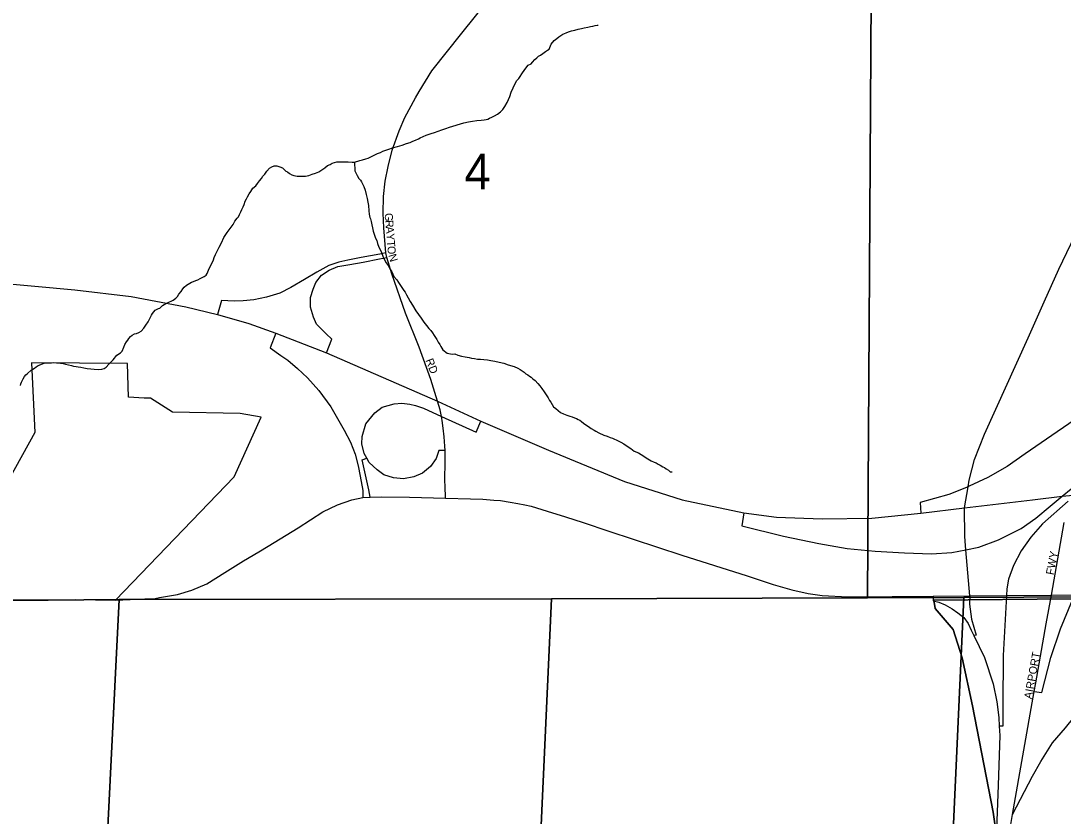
# Model space of a CAD drawing. Extents: x 2010165 to 2382125, y 1060529 to 1407316.
# Drawn here: x 2146217 to 2152727, y 1244739 to 1249704 of the extents above; entities that cross this region are included whole.
import ezdxf

# ---------------------------------------------------------------- set-up
doc = ezdxf.new("R2010")
doc.units = 0
for name, color, linetype in [('GM_X_City_Street', 7, 'Continuous'), ('GM_X_City_Street_Text', 7, 'Continuous'), ('GM_X_Corporation', 7, 'Continuous'), ('GM_X_Interchange_Ramps', 7, 'Continuous'), ('GM_X_Interstate_Route', 7, 'Continuous'), ('GM_X_Minor_River', 7, 'Continuous'), ('GM_X_Section', 7, 'Continuous'), ('GM_X_Section_Text', 7, 'Continuous'), ('GM_X_State_Route', 7, 'Continuous')]:
    doc.layers.add(name, color=color, linetype=linetype)

msp = doc.modelspace()

# ---------------------------------------------------------------- linework, layer by layer
at = {"layer": 'GM_X_City_Street'}
for points in [[(2148705.3, 1249263.5), (2148782.9, 1249391.8), (2148971.4, 1249627.1), (2149244.4, 1249968.5), (2149566.8, 1250337.8), (2149744.1, 1250550), (2149810.3, 1250647.6), (2149864.3, 1250752.2), (2149904.4, 1250860.3), (2149937, 1250974.5), (2149998, 1251300.5), (2150083.5, 1251782.8)], [(2148859.8, 1247107), (2148854.4, 1247159.9), (2148847.9, 1247208.4), (2148843, 1247234.5), (2148835.4, 1247275.8), (2148818.7, 1247328.9), (2148777.8, 1247463.9), (2148703.5, 1247666.6), (2148619.2, 1247878.6), (2148534.2, 1248124.8), (2148501.8, 1248226.4), (2148496.2, 1248255.4), (2148483.5, 1248412.5), (2148480.6, 1248503.1), (2148482.1, 1248606.5), (2148492, 1248702.8), (2148510.4, 1248794.8), (2148536.1, 1248895.5), (2148580, 1249016.6), (2148615.6, 1249100.9), (2148680.9, 1249223.2), (2148705.3, 1249263.5)], [(2148869.9, 1246722.9), (2148866.4, 1246800.4), (2148865.1, 1246829.1), (2148866.4, 1246958.4), (2148866, 1247021.3), (2148865.8, 1247048.4), (2148859.8, 1247107)], [(2152621.6, 1245939.2), (2152653.4, 1246119.1), (2152733.6, 1246572.2)], [(2152556.3, 1245569.9), (2152621.6, 1245939.2)], [(2152411, 1244747.8), (2152547, 1245517.1), (2152556.3, 1245569.9)]]:
    msp.add_lwpolyline(points, dxfattribs=at)
at = {"layer": 'GM_X_Corporation'}
for points in [[(2145721.8, 1246089.3), (2146557.6, 1246091.4), (2146807.3, 1246086.3), (2147548.1, 1246856.1), (2147717.4, 1247229.8), (2147586.4, 1247252.2), (2147163.9, 1247261.4), (2147026.1, 1247348.8), (2146986, 1247348), (2146889.8, 1247354.1), (2146883.7, 1247564.5), (2146283, 1247568.4), (2146303.5, 1247133.8), (2146005.5, 1246598.5)], [(2152310.6, 1244620.1), (2152289.8, 1244764), (2152160.8, 1245427.1), (2152096.9, 1245726.6), (2152039.4, 1245903.8), (2151926.8, 1246035.9), (2151919.8, 1246085.9), (2152779.7, 1246094.4)], [(2152779.7, 1246094.4), (2151919.8, 1246085.9), (2151926.8, 1246035.9), (2152039.4, 1245903.8), (2152096.9, 1245726.6), (2152160.8, 1245427.1), (2152289.8, 1244764), (2152310.6, 1244620.1)]]:
    msp.add_lwpolyline(points, dxfattribs=at)
at = {"layer": 'GM_X_Interchange_Ramps'}
for points in [[(2148496.2, 1248255.4), (2148458.9, 1248246.8), (2148342.3, 1248225.4), (2148258.9, 1248210.1), (2148202.3, 1248198.1), (2148140.9, 1248176.1), (2148066.3, 1248134.1), (2147989.1, 1248089), (2147903.6, 1248038.8), (2147834.2, 1248003.9), (2147751.3, 1247977.7), (2147672.7, 1247962.4), (2147605.1, 1247955.9), (2147548.4, 1247953.7), (2147509.1, 1247955.9), (2147469.9, 1247958.1), (2147445.6, 1247870.8)], [(2148126.6, 1247630.8), (2148159.3, 1247715.9), (2148122.9, 1247749.3), (2148063.3, 1247809.7), (2148043.7, 1247853.3), (2148026.2, 1247916.6), (2148026.3, 1247976.8), (2148041.5, 1248027.9), (2148058.9, 1248069.3), (2148093.8, 1248115.2), (2148141.8, 1248147.9), (2148196.9, 1248169.5), (2148270.6, 1248182.8), (2148355.6, 1248198.1), (2148456, 1248217.7), (2148501.8, 1248226.4)], [(2147809.6, 1247753.5), (2147773.6, 1247662.1), (2147840.3, 1247615.5), (2147884.3, 1247584.8), (2147944.3, 1247533.5), (2148007.6, 1247475.5), (2148077.6, 1247396.2), (2148152.3, 1247294.2), (2148235.6, 1247148.2), (2148276.2, 1247072.9), (2148304.4, 1246999.2), (2148323.6, 1246926.3), (2148337, 1246861.2), (2148352.4, 1246771), (2148351.8, 1246728.1)], [(2150732.1, 1246631.2), (2150720, 1246551.3), (2150979.3, 1246486.8), (2151201.7, 1246441.1), (2151378, 1246409.1), (2151552.9, 1246392), (2151736.2, 1246381.6), (2151904.2, 1246375.8), (2152032, 1246384.3), (2152119.1, 1246401.5), (2152199.4, 1246417.3), (2152323.7, 1246464.4), (2152464, 1246533.9), (2152556.8, 1246599.1), (2152645.8, 1246672.9), (2152720.3, 1246735.4), (2152776.9, 1246782.9), (2153276.7, 1247202.3), (2153303.4, 1247223.8), (2153452.3, 1247343.7), (2153542.4, 1247405.7), (2153625, 1247452), (2153693.6, 1247486.4), (2153668.7, 1247553.2)], [(2153547.8, 1247510.5), (2153538, 1247546.7), (2153138.2, 1247413.1), (2153032.3, 1247363.9), (2152929.6, 1247302.3), (2152490.1, 1247000.1), (2152377.2, 1246920.5), (2152255.9, 1246852.4), (2152140.3, 1246797.8), (2152132.8, 1246794.8), (2152012.5, 1246745.7), (2151834.7, 1246697.4), (2151838.2, 1246630.9)], [(2148866, 1247021.3), (2148828.4, 1247021.7), (2148809.9, 1246970.8), (2148775.3, 1246922.3), (2148724.4, 1246880.8), (2148671.3, 1246857.7), (2148606.7, 1246843.8), (2148544.3, 1246850.8), (2148484.3, 1246869.2), (2148442.7, 1246901.6), (2148391.9, 1246945.4), (2148377.4, 1246973.2), (2148361.9, 1247003.2), (2148347.3, 1247062.5), (2148348, 1247109.5), (2148371.1, 1247187.9), (2148426.6, 1247256), (2148472.7, 1247291.9), (2148549.4, 1247313.7), (2148596.6, 1247316.7), (2148646.4, 1247311.1), (2148681.6, 1247302.9), (2148732.1, 1247285.1), (2148843, 1247234.5), (2149059.9, 1247135.7), (2149090.1, 1247204.3)], [(2148399.2, 1246729.9), (2148390.7, 1246775.8), (2148348.5, 1246963.7), (2148377.4, 1246973.2)], [(2152547, 1245517.1), (2152593.1, 1245510.1), (2152649.9, 1245729.4), (2152709.9, 1245907.1), (2152784.5, 1246090), (2152797.6, 1246120.6), (2152838.3, 1246216), (2152902.4, 1246317.8), (2152966.8, 1246404.9), (2153031.3, 1246487.1), (2153108.2, 1246557.3), (2153214.5, 1246633), (2153321.1, 1246694), (2153432.9, 1246740.4), (2153520.7, 1246761.7), (2153559.2, 1246770.7), (2153553.8, 1246822.3)], [(2152759.2, 1246705.7), (2152598.6, 1246563.8), (2152526, 1246480.5), (2152463.9, 1246394.9), (2152416.4, 1246302.9), (2152385.9, 1246219), (2152374.7, 1246158.1), (2152372.4, 1246116.1), (2152352.7, 1245741.3), (2152351, 1245431.8), (2152349.4, 1245301.2), (2152327.8, 1245299.8)], [(2151915, 1246111.3), (2151914.9, 1246082.3), (2151950.9, 1246074.6), (2151990.2, 1246057.5), (2152032.9, 1246033.1), (2152069.2, 1246008.5), (2152105.7, 1245977.7), (2152132.8, 1245941.3), (2152152.6, 1245899.6), (2152170.1, 1245866.2), (2152235.7, 1245728.3), (2152290.5, 1245565.3), (2152312.4, 1245453), (2152324.3, 1245355.2), (2152327.8, 1245299.8), (2152331.5, 1245242.6), (2152320.8, 1244931.1), (2152308.9, 1244597.7), (2152384.4, 1244584.3)], [(2152144, 1246113.6), (2152143, 1246062.2), (2152155.5, 1245967.8), (2152183.2, 1245869.4), (2152170.1, 1245866.2)]]:
    msp.add_lwpolyline(points, dxfattribs=at)
at = {"layer": 'GM_X_Interstate_Route'}
for points in [[(2145362.6, 1248149.4), (2145699, 1248127.3), (2145984, 1248075.9), (2146303.1, 1248046.5)], [(2146303.1, 1248046.5), (2146553.5, 1248023.5), (2146904.8, 1247982.1), (2147246.3, 1247918.8), (2147445.6, 1247870.8), (2147640.3, 1247814.1), (2147809.6, 1247753.5), (2148126.6, 1247630.8), (2148818.7, 1247328.9)], [(2148818.7, 1247328.9), (2149090.1, 1247204.3), (2149512.2, 1247022.9), (2149986.3, 1246827.7), (2150348.1, 1246712.4), (2150732.1, 1246631.2)], [(2150732.1, 1246631.2), (2150936.8, 1246605.6), (2151222.2, 1246594.1), (2151531.1, 1246599.9), (2151838.2, 1246630.9), (2152111.5, 1246663.3), (2152534.6, 1246713.4)], [(2152534.6, 1246713.4), (2152720.3, 1246735.4), (2152767.2, 1246741), (2152804.1, 1246745.3), (2152815.8, 1246746.7), (2153017.1, 1246767.3)]]:
    msp.add_lwpolyline(points, dxfattribs=at)
at = {"layer": 'GM_X_Minor_River'}
for points in [[(2148597.8, 1248928.2), (2148625.7, 1248938.7), (2148647.6, 1248945.2), (2148665.5, 1248953.6), (2148681.4, 1248959.9), (2148699.4, 1248966.2), (2148711.3, 1248972.5), (2148729.2, 1248980.8), (2148749.1, 1248989.3), (2148779, 1248999.9), (2148801, 1249006.3), (2148822.9, 1249014.8), (2148846.8, 1249023.2), (2148870.8, 1249031.7), (2148894.7, 1249040.2), (2148982.5, 1249068), (2149012.5, 1249072.6), (2149038.5, 1249077.1), (2149064.5, 1249081.6), (2149092.5, 1249084.1), (2149110.5, 1249086.5), (2149122.5, 1249088.8), (2149132.5, 1249090.9), (2149144.5, 1249095.2), (2149158.4, 1249101.5), (2149174.3, 1249111.8), (2149194.2, 1249122.2), (2149212, 1249136.6), (2149227.7, 1249151), (2149239.4, 1249169.2), (2149255, 1249193.6), (2149262.7, 1249211.8), (2149270.4, 1249232.1), (2149279.9, 1249258.3), (2149291.5, 1249284.6), (2149303.1, 1249308.9), (2149314.7, 1249331.2), (2149326.5, 1249343.5), (2149336.3, 1249355.8), (2149346, 1249374), (2149363.6, 1249400.4), (2149385.2, 1249426.9), (2149403.1, 1249435.3), (2149412.9, 1249445.5), (2149426.6, 1249461.8), (2149438.5, 1249472.1), (2149450.3, 1249482.4), (2149462.2, 1249490.6), (2149476.1, 1249500.9), (2149493.9, 1249513.3), (2149505.8, 1249521.6), (2149515.7, 1249527.8), (2149529.2, 1249558.1), (2149548.8, 1249580.6), (2149564.7, 1249592.9), (2149576.5, 1249603.2), (2149602.3, 1249619.7), (2149622.2, 1249628.1), (2149638.2, 1249634.5), (2149656.1, 1249640.8), (2149676.1, 1249645.2), (2149698, 1249651.7), (2149718, 1249656.1), (2149736, 1249660.4), (2149758, 1249664.9), (2149774, 1249669.2), (2149790, 1249671.5), (2149804, 1249673.8), (2149816, 1249676), (2149822, 1249676.1)], [(2147101.3, 1247926.1), (2147123.1, 1247938.6), (2147159, 1247955.3), (2147168.9, 1247959.5), (2147184.7, 1247971.9), (2147194.6, 1247982.1), (2147204.3, 1247998.3), (2147218, 1248014.6), (2147227.8, 1248030.9), (2147237.6, 1248041.1), (2147251.4, 1248053.4), (2147261.4, 1248059.6), (2147271.3, 1248065.8), (2147283.2, 1248072.1), (2147295.2, 1248076.3), (2147309.1, 1248082.6), (2147321.1, 1248086.9), (2147337, 1248095.2), (2147348.9, 1248101.4), (2147360.8, 1248107.7), (2147374.7, 1248116), (2147380.5, 1248126.1), (2147388.2, 1248146.3), (2147399.8, 1248170.7), (2147411.4, 1248192.9), (2147419.1, 1248211.2), (2147424.8, 1248227.3), (2147432.5, 1248245.5), (2147442.1, 1248265.8), (2147455.7, 1248290.1), (2147469.3, 1248318.5), (2147484.7, 1248350.9), (2147504.2, 1248381.4), (2147543.4, 1248432.3), (2147553.1, 1248452.6), (2147566.8, 1248470.9), (2147576.6, 1248481.1), (2147582.4, 1248495.3), (2147590.1, 1248511.5), (2147597.8, 1248525.7), (2147605.6, 1248541.9), (2147611.3, 1248558), (2147616.9, 1248578.2), (2147626.7, 1248592.4), (2147632.5, 1248604.6), (2147642.2, 1248622.8), (2147653.9, 1248639.1), (2147665.6, 1248659.4), (2147683.4, 1248673.8), (2147695.2, 1248688.1), (2147706.9, 1248704.4), (2147718.7, 1248718.6), (2147728.4, 1248734.9), (2147740.2, 1248747.1), (2147753.9, 1248765.5), (2147769.6, 1248783.8), (2147783.5, 1248792.1), (2147799.5, 1248798.5), (2147815.5, 1248798.8), (2147833.7, 1248793.1), (2147849.9, 1248785.4), (2147862.1, 1248775.6), (2147872.3, 1248765.7), (2147882.4, 1248761.9), (2147894.7, 1248750.1), (2147908.9, 1248742.4), (2147921, 1248738.6), (2147931.1, 1248736.8), (2147943.1, 1248735), (2147953.2, 1248733.2), (2147995.3, 1248734), (2148015.3, 1248738.4), (2148035.2, 1248746.8), (2148057.2, 1248753.2), (2148077.1, 1248761.6), (2148096.9, 1248774.1), (2148114.8, 1248786.4), (2148132.5, 1248800.8), (2148148.5, 1248807.1), (2148160.4, 1248815.4), (2148176.3, 1248819.7), (2148190.3, 1248824), (2148208.4, 1248824.4), (2148232.5, 1248822.8), (2148260.6, 1248823.4), (2148286.7, 1248821.8), (2148300.7, 1248822.1), (2148334.6, 1248832.8), (2148350.6, 1248837.1), (2148370.6, 1248841.5), (2148386.6, 1248845.8), (2148402.5, 1248854.2), (2148424.4, 1248864.6), (2148444.2, 1248875), (2148462.2, 1248881.4), (2148478.1, 1248889.7), (2148496, 1248896.1), (2148516, 1248902.5), (2148537.9, 1248911), (2148569.8, 1248919.6), (2148597.8, 1248928.2)], [(2148300.7, 1248822.1), (2148303.7, 1248768), (2148316.3, 1248738.1), (2148328.7, 1248720.3), (2148339, 1248708.5), (2148345.2, 1248698.5), (2148351.4, 1248686.6), (2148359.8, 1248668.7), (2148366.2, 1248646.8), (2148372.7, 1248618.8), (2148379.2, 1248594.8), (2148383.6, 1248572.8), (2148388, 1248550.8), (2148390.7, 1248516.8), (2148393.1, 1248496.8), (2148395.3, 1248486.8), (2148397.4, 1248476.8), (2148399.6, 1248466.8), (2148404, 1248450.8), (2148417.1, 1248390.8), (2148432, 1248347), (2148440.3, 1248333.1), (2148444.6, 1248313.1), (2148453.1, 1248291.2), (2148461.4, 1248275.3), (2148469.8, 1248257.4), (2148478.2, 1248235.5), (2148488.7, 1248211.6), (2148499, 1248193.7), (2148511.4, 1248175.9), (2148521.8, 1248156), (2148534.2, 1248136.2), (2148546.8, 1248108.4), (2148565.3, 1248086.6), (2148575.6, 1248070.8), (2148600.4, 1248033.1), (2148608.6, 1248021.2), (2148616.9, 1248009.4), (2148625.2, 1247993.5), (2148635.6, 1247973.6), (2148648, 1247951.8), (2148662.5, 1247927.9), (2148683.2, 1247894.2), (2148699.7, 1247870.5), (2148716.2, 1247846.7), (2148734.7, 1247823), (2148751.2, 1247801.2), (2148765.5, 1247783.4), (2148777.8, 1247769.6), (2148788.1, 1247755.8), (2148798.5, 1247739.9), (2148806.7, 1247726), (2148815, 1247714.1), (2148823.3, 1247698.2), (2148833.6, 1247682.4), (2148839.9, 1247670.4), (2148846.1, 1247660.5), (2148852.3, 1247650.6), (2148878.8, 1247629), (2148911, 1247623.6), (2148927, 1247623.9), (2148945.2, 1247616.3), (2148969.4, 1247610.7), (2148991.6, 1247607.1), (2149015.8, 1247601.6), (2149031.9, 1247597.9), (2149050, 1247596.2), (2149068.1, 1247592.5), (2149088.2, 1247590.9), (2149108.3, 1247589.3), (2149130.4, 1247587.7), (2149152.5, 1247584.1), (2149176.7, 1247578.6), (2149204.9, 1247573.1), (2149233.1, 1247567.6), (2149261.4, 1247556.1), (2149297.8, 1247544.8), (2149320, 1247535.1), (2149336.2, 1247527.4), (2149360.6, 1247509.8), (2149370.8, 1247500), (2149383, 1247494.2), (2149393.2, 1247486.4), (2149403.3, 1247478.6), (2149413.6, 1247468.7), (2149429.8, 1247459), (2149446.2, 1247439.2), (2149458.5, 1247425.4), (2149470.9, 1247407.6), (2149485.3, 1247387.8), (2149497.7, 1247368), (2149510.1, 1247350.1), (2149518.4, 1247334.3), (2149526.6, 1247322.4), (2149534.9, 1247308.5), (2149543.2, 1247294.6), (2149557.5, 1247282.8), (2149571.8, 1247271.1), (2149588, 1247259.3), (2149606.3, 1247249.6), (2149626.5, 1247242)], [(2146213.5, 1247427.4), (2146217.4, 1247437.5), (2146221.2, 1247447.6), (2146230.8, 1247467.9), (2146238.6, 1247484.1), (2146248.4, 1247494.3), (2146258.3, 1247502.5), (2146280, 1247523), (2146291.9, 1247529.3), (2146301.8, 1247535.5), (2146311.7, 1247543.7), (2146325.6, 1247552), (2146361.5, 1247566.7), (2146375.5, 1247569), (2146391.5, 1247569.3), (2146407.6, 1247569.6), (2146421.6, 1247569.9), (2146439.7, 1247568.2), (2146451.7, 1247568.5), (2146463.8, 1247566.7), (2146479.9, 1247565), (2146496, 1247561.3), (2146514.2, 1247555.6), (2146532.3, 1247551.9), (2146546.4, 1247548.2), (2146562.5, 1247546.5), (2146574.6, 1247544.7), (2146590.7, 1247541), (2146610.8, 1247537.4), (2146631, 1247533.8), (2146653.1, 1247532.2), (2146675.2, 1247528.6), (2146701.3, 1247527.1), (2146723.4, 1247529.5), (2146737.3, 1247533.8), (2146749.2, 1247542.1), (2146766.9, 1247560.5), (2146792.5, 1247587), (2146816.1, 1247615.6), (2146839.9, 1247632.1), (2146849.7, 1247642.3), (2146859.3, 1247666.6), (2146867, 1247682.8), (2146876.7, 1247699), (2146884.5, 1247711.2), (2146890.4, 1247721.4), (2146902.2, 1247733.6), (2146912.1, 1247741.9), (2146926, 1247750.1), (2146938, 1247752.4), (2146953.9, 1247758.7), (2146967.8, 1247767), (2146985.5, 1247785.4), (2146997.2, 1247803.7), (2147010.9, 1247824), (2147032.2, 1247866.6), (2147038, 1247876.7), (2147055.7, 1247897.1), (2147075.6, 1247907.6), (2147085.5, 1247909.8), (2147101.3, 1247926.1)], [(2149626.5, 1247242), (2149644.6, 1247236.3), (2149660.8, 1247230.6), (2149675, 1247224.9), (2149687.1, 1247221.1), (2149697.2, 1247215.3), (2149707.3, 1247211.4), (2149719.5, 1247201.6), (2149731.8, 1247191.8), (2149746, 1247182.1), (2149762.3, 1247170.3), (2149778.5, 1247158.6), (2149796.8, 1247148.9), (2149808.9, 1247143.1), (2149827.2, 1247131.4), (2149857.5, 1247118), (2149879.8, 1247110.4), (2149898, 1247102.7), (2149912.1, 1247099), (2149948.5, 1247081.6), (2149964.7, 1247073.9), (2149983, 1247062.2), (2150003.3, 1247048.5), (2150025.7, 1247032.9), (2150048.1, 1247017.3), (2150074.4, 1247005.8), (2150090.6, 1246996), (2150100.7, 1246990.2), (2150117, 1246980.5), (2150133.2, 1246968.8), (2150143.4, 1246962.9), (2150153.5, 1246957.1), (2150171.7, 1246949.4), (2150183.9, 1246943.6), (2150198.1, 1246935.9), (2150210.2, 1246930.1), (2150226.5, 1246920.4), (2150236.6, 1246914.5), (2150246.8, 1246906.7), (2150261, 1246898.9), (2150273.2, 1246889.1), (2150285.3, 1246887.4), (2150285.3, 1246887.4)]]:
    msp.add_lwpolyline(points, dxfattribs=at)
at = {"layer": 'GM_X_Section'}
for points in [[(2145755.1, 1251562.6), (2151537.5, 1251558.4), (2151505.5, 1246102.3), (2149530.7, 1246095.7), (2146829.9, 1246090.5), (2145721.8, 1246081.2)], [(2151537.5, 1251558.4), (2157362.6, 1251549), (2157328.9, 1246108.9), (2157281.9, 1246108.8), (2154728, 1246118.3), (2152107.3, 1246104.5), (2151505.5, 1246102.3)], [(2145721.8, 1246081.2), (2146829.9, 1246090.5), (2146747.7, 1244419.5), (2144175.5, 1244431.8), (2144233.9, 1246072.8)], [(2146829.9, 1246090.5), (2149530.7, 1246095.7), (2149454.9, 1244406.6), (2146747.7, 1244419.5)], [(2151505.5, 1246102.3), (2152107.3, 1246104.5), (2152029.6, 1244415.8), (2149454.9, 1244406.6), (2149530.7, 1246095.7)], [(2152107.3, 1246104.5), (2154728, 1246118.3), (2154635.6, 1244425.2), (2152029.6, 1244415.8)]]:
    msp.add_lwpolyline(points, close=True, dxfattribs=at)
at = {"layer": 'GM_X_State_Route'}
for points in [[(2152113.8, 1246485.7), (2152110.7, 1246658.4), (2152111.5, 1246663.3), (2152132.8, 1246794.8), (2152139.3, 1246835.4), (2152173.5, 1246966.1), (2152235.3, 1247123.3), (2152507.6, 1247725), (2152609.1, 1247949.8), (2152700.6, 1248152.6), (2152827.9, 1248417.7), (2152953.2, 1248682.7), (2153062.7, 1248913.6), (2153142.2, 1249090.3), (2153221.8, 1249263), (2153268.7, 1249376.1), (2153273.1, 1249386.8)], [(2147702.3, 1246388.6), (2147761.9, 1246424.3), (2147947.8, 1246538.2), (2148103, 1246638.2), (2148193.5, 1246682.8), (2148284, 1246713.8), (2148351.8, 1246728.1), (2148399.2, 1246729.9), (2148468.7, 1246731.2), (2148643.5, 1246729.9), (2148869.9, 1246722.9)], [(2148869.9, 1246722.9), (2149026.2, 1246719.9), (2149102.2, 1246718.3), (2149170.4, 1246712.3), (2149213, 1246708.5), (2149272.1, 1246699.4), (2149320.7, 1246691), (2149364, 1246682.7), (2149405, 1246673.6), (2149504.4, 1246643.4), (2149618, 1246606.9), (2149728.2, 1246572.1), (2149889.4, 1246518.1), (2150346, 1246367.3), (2150753, 1246238.4), (2150915.2, 1246184), (2151032, 1246151.6), (2151135.2, 1246128.6), (2151220.9, 1246116.7), (2151382.1, 1246108.7), (2151658.1, 1246110)], [(2152144, 1246113.6), (2152119.1, 1246401.5), (2152114.3, 1246456.3), (2152113.8, 1246485.7)], [(2145717.6, 1246089.4), (2146060.7, 1246085.6), (2146557.6, 1246091.4), (2146807.4, 1246086.3), (2146991, 1246095.3), (2147055.3, 1246097.8), (2147082.1, 1246102.7), (2147194.2, 1246123.1), (2147284.3, 1246148.4), (2147377.5, 1246189.4), (2147491.2, 1246260.5), (2147607.2, 1246331.8), (2147702.3, 1246388.6)], [(2152144, 1246113.6), (2152372.4, 1246116.1), (2152653.4, 1246119.1), (2152797.6, 1246120.6), (2152835.4, 1246121)], [(2152392.9, 1244636.7), (2152411, 1244747.8), (2152535.7, 1244988.9), (2152587.2, 1245079.6), (2152660.4, 1245196), (2152742.3, 1245290.5), (2152846.1, 1245419.2), (2152945.9, 1245535.8), (2153057.6, 1245662.5), (2153147.4, 1245783.1), (2153191.2, 1245857.4), (2153223.7, 1245916.2), (2153243.4, 1245972.6), (2153250.2, 1246125.4)], [(2151658.1, 1246110), (2151915, 1246111.3), (2152144, 1246113.6)]]:
    msp.add_lwpolyline(points, dxfattribs=at)

# ---------------------------------------------------------------- texts
at = {"layer": 'GM_X_City_Street_Text'}
for s, rotation, p in [('G', 274.70376, (2148488.5, 1248501.9)), ('R', 274.69305, (2148492.1, 1248458)), ('A', 274.68975, (2148495.3, 1248418.6)), ('Y', 274.68198, (2148498.9, 1248374.7)), ('T', 274.69405, (2148502.5, 1248330.8)), ('O', 274.68975, (2148505.4, 1248295.8)), ('N', 286.88194, (2148511.2, 1248240.5)), ('RD', 291.24876, (2148743, 1247584.9)), ('FWY', 79.04439, (2152667.5, 1246241.3)), ('AIRPORT', 79.61201, (2152531, 1245466.5))]:
    msp.add_text(s, height=50, rotation=rotation, dxfattribs=at).set_placement(p)
at = {"layer": 'GM_X_Section_Text'}
msp.add_text('4', height=221, rotation=0.00001, dxfattribs=at).set_placement((2148987.3, 1248652.7))

doc.saveas('drawing.dxf')
